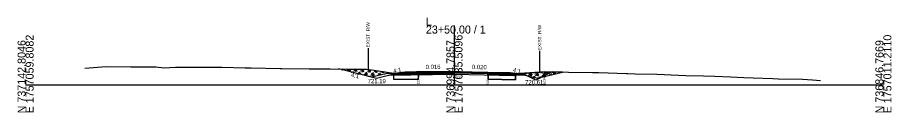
# Model space of a CAD drawing. Extents: x -26 to 4303, y -10 to 9577.
# Drawn here: x 997.2 to 1302.8, y 3490.3 to 3523.5 of the extents above; entities that cross this region are included whole.
import ezdxf

# ---------------------------------------------------------------- set-up
doc = ezdxf.new("R2010")
doc.units = 0
for name, color, linetype in [('Exist CMT Pavement', 7, 'Continuous'), ('Old_Level_10', 7, 'Continuous'), ('Old_Level_2', 7, 'Continuous'), ('Pattern 3', 7, 'Continuous'), ('Prop CMT Conc Surface', 7, 'Continuous'), ('Prop CMT Concrete Structures', 7, 'Continuous'), ('Prop CMT Concrete Wall', 7, 'Continuous'), ('Prop CMT Pvmt Course 1', 7, 'Continuous'), ('Prop CMT Pvmt Course 1 CG', 7, 'Continuous'), ('Prop CMT Pvmt Course 2', 7, 'Continuous'), ('Prop CMT Pvmt Course 2 Wedge', 7, 'Continuous'), ('Prop CMT Pvmt Course 3', 7, 'Continuous'), ('Prop CMT Pvmt Surface', 7, 'Continuous'), ('Prop CMT Pvmt Wedge Surface 1', 7, 'Continuous'), ('Prop CMT Shld Paved Course 1', 7, 'Continuous'), ('Prop CMT Shld Paved Course 2', 7, 'Continuous'), ('Prop CMT Shld Paved Course 3', 7, 'Continuous'), ('Prop CMT Slope Grass', 7, 'Continuous'), ('Prop CMT Subgrade Earthwork', 7, 'Continuous'), ('Prop Road Sect_ Recs - UC Shallow (Outline)', 7, 'Continuous'), ('Prop Shade Light', 7, 'Continuous'), ('Prop XS DDE Elevations', 7, 'Continuous'), ('Prop XS Ditch Standard Text', 7, 'Continuous'), ('Prop XS Earthwork Shape', 7, 'Continuous'), ('Prop XS Hydro Elevations', 7, 'Continuous'), ('Prop XS SE Text', 7, 'Continuous'), ('Prop XS Side Slope Text', 7, 'Continuous')]:
    doc.layers.add(name, color=color, linetype=linetype)

msp = doc.modelspace()

# ---------------------------------------------------------------- linework, layer by layer
at = {"layer": 'Exist CMT Pavement'}
for points in [[(1150, 3504.61), (1134.74, 3504.37)], [(1150, 3504.61), (1167.35, 3504.27)]]:
    msp.add_lwpolyline(points, dxfattribs=at)
at = {"layer": 'Old_Level_10'}
for p, q in [((1174.21, 3503.75), (1172.21, 3503.85)), ((1178.41, 3501.61), (1174.21, 3503.71)), ((1184.16, 3504.49), (1178.41, 3501.61))]:
    msp.add_line(p, q, dxfattribs=at)
at = {"layer": 'Old_Level_2'}
for p, q in [((1150, 3500), (1150, 3520.68)), ((1150, 3500), (1150, 3520.68)), ((1000, 3500), (1150, 3500)), ((1000, 3500), (1150, 3500)), ((1150, 3500), (1300, 3500)), ((1150, 3500), (1300, 3500))]:
    msp.add_line(p, q, dxfattribs=at)
at = {"layer": 'Pattern 3'}
for p, q in [((1110.45, 3505.26), (1111.3, 3505.49)), ((1110.6, 3505.5), (1110.97, 3505.13)), ((1110.8, 3505.49), (1110.72, 3505.19)), ((1112.51, 3505.06), (1113.72, 3505.38)), ((1112.87, 3505.47), (1113.55, 3504.78)), ((1113.18, 3505.46), (1112.95, 3504.63)), ((1113.91, 3504.43), (1113.95, 3504.38)), ((1114.51, 3504.59), (1114.42, 3504.27)), ((1114.86, 3504.94), (1116.07, 3505.27)), ((1114.93, 3504.14), (1114.95, 3504.15)), ((1115.12, 3505.46), (1115.91, 3504.66)), ((1115.56, 3505.45), (1115.31, 3504.5)), ((1116.26, 3504.31), (1116.93, 3503.64)), ((1116.37, 3503.78), (1117.31, 3504.03)), ((1116.87, 3504.47), (1116.66, 3503.71)), ((1117.22, 3504.82), (1118.43, 3505.15)), ((1117.38, 3505.43), (1118.27, 3504.54)), ((1117.95, 3505.44), (1117.66, 3504.38)), ((1118.46, 3503.59), (1119.67, 3503.91)), ((1118.62, 3504.19), (1119.5, 3503.31)), ((1119.22, 3504.35), (1118.9, 3503.15)), ((1119.58, 3504.71), (1120.78, 3505.03)), ((1119.74, 3505.31), (1120.62, 3504.43)), ((1120.3, 3505.3), (1120.02, 3504.26)), ((1120.46, 3503.11), (1120.37, 3502.78)), ((1120.81, 3503.47), (1122.02, 3503.79)), ((1120.98, 3504.07), (1121.86, 3503.19)), ((1121.58, 3504.23), (1121.26, 3503.03)), ((1121.93, 3504.59), (1123.1, 3504.9)), ((1122.26, 3505.03), (1122.98, 3504.31)), ((1122.6, 3504.98), (1122.38, 3504.15)), ((1123.17, 3503.35), (1124.38, 3503.67)), ((1123.33, 3503.95), (1123.93, 3503.35)), ((1123.94, 3504.12), (1123.72, 3503.3)), ((1124.29, 3504.47), (1124.87, 3504.62)), ((1124.89, 3504.62), (1124.73, 3504.03)), ((1124.91, 3504.62), (1125.34, 3504.19)), ((1125.69, 3503.84), (1125.72, 3503.8)), ((1126.29, 3504), (1126.26, 3503.86)), ((1127.18, 3504.27), (1127.09, 3503.91)), ((1127.55, 3504.21), (1127.69, 3504.07)), ((1128.65, 3503.88), (1128.65, 3503.87)), ((1129.48, 3503.92), (1129.47, 3503.87)), ((1130.03, 3503.97), (1130.05, 3503.95)), ((1131.93, 3504.15), (1131.86, 3503.87)), ((1132.07, 3504.16), (1132.36, 3503.87)), ((1133.72, 3504), (1134.92, 3504.32)), ((1134.12, 3504.35), (1134.6, 3503.88)), ((1134.38, 3504.38), (1134.24, 3503.88)), ((1136.09, 3503.88), (1137.28, 3504.2)), ((1136.23, 3504.48), (1136.83, 3503.88)), ((1136.83, 3504.6), (1136.63, 3503.88)), ((1162.38, 3504.15), (1162.28, 3503.77)), ((1162.69, 3504.13), (1162.89, 3503.93)), ((1163.84, 3503.74), (1163.82, 3503.64)), ((1164.73, 3503.99), (1164.64, 3503.65)), ((1165.09, 3503.96), (1165.24, 3503.81)), ((1166.2, 3503.62), (1166.19, 3503.59)), ((1167.07, 3503.82), (1167.01, 3503.57)), ((1167.5, 3503.79), (1167.6, 3503.69)), ((1169.42, 3503.65), (1169.38, 3503.53)), ((1169.85, 3503.68), (1169.95, 3503.58)), ((1171.27, 3503.74), (1171.49, 3503.8)), ((1171.85, 3503.82), (1171.76, 3503.48)), ((1171.94, 3503.83), (1172.3, 3503.47)), ((1173.62, 3503.62), (1174.83, 3503.94)), ((1174.03, 3503.98), (1174.67, 3503.34)), ((1174.28, 3504), (1174.13, 3503.43)), ((1175.62, 3503.15), (1175.61, 3503.1)), ((1175.98, 3503.5), (1177.19, 3503.82)), ((1176.14, 3504.1), (1177.02, 3503.22)), ((1176.72, 3504.17), (1176.42, 3503.06)), ((1177.55, 3504.24), (1177.54, 3504.18)), ((1178.33, 3503.38), (1179.54, 3503.71)), ((1178.5, 3503.99), (1179.38, 3503.1)), ((1179.1, 3504.15), (1178.78, 3502.94)), ((1179.99, 3504.41), (1179.9, 3504.06)), ((1180.29, 3504.43), (1180.5, 3504.22)), ((1180.69, 3503.26), (1181.9, 3503.59)), ((1180.85, 3503.87), (1181.74, 3502.98)), ((1181.46, 3504.03), (1181.13, 3502.82)), ((1181.81, 3504.38), (1182.31, 3504.52)), ((1182.41, 3504.52), (1182.25, 3503.94)), ((1182.44, 3504.52), (1182.86, 3504.1)), ((1183.21, 3503.75), (1183.57, 3503.39)), ((1183.81, 3503.91), (1183.68, 3503.42)), ((1184.17, 3504.26), (1184.95, 3504.47)), ((1184.78, 3504.48), (1184.61, 3503.82)), ((1184.72, 3504.48), (1185.21, 3503.98)), ((1186.52, 3504.15), (1187.58, 3504.43)), ((1186.99, 3504.44), (1187.15, 3504.29)), ((1187.16, 3504.44), (1187.12, 3504.28)), ((1119.86, 3502.95), (1119.92, 3502.89)), ((1120.85, 3502.66), (1120.9, 3502.67)), ((1177.38, 3502.87), (1177.66, 3502.58)), ((1177.98, 3503.03), (1177.85, 3502.54)), ((1178.05, 3502.49), (1178.42, 3502.59)), ((1179.73, 3502.75), (1179.99, 3502.5)), ((1180.34, 3502.91), (1180.24, 3502.56))]:
    msp.add_line(p, q, dxfattribs=at)
for points in [[(1121, 3502.62), (1109.45, 3505.51), (1113.28, 3505.46), (1119.26, 3505.44), (1121.87, 3505.09), (1125.66, 3504.5), (1129.45, 3503.92), (1133, 3504.25), (1136.84, 3504.6), (1137.45, 3504.64), (1137.45, 3503.89), (1129.62, 3503.87), (1128.62, 3503.87), (1125.95, 3503.86)], [(1179, 3502.25), (1187.72, 3504.43), (1181.59, 3504.53), (1178.1, 3504.28), (1172.9, 3503.9), (1169.41, 3503.65), (1166.49, 3503.86), (1163.07, 3504.1), (1161.77, 3504.19), (1161.77, 3503.68), (1171.39, 3503.49), (1174.28, 3503.43)]]:
    msp.add_lwpolyline(points, close=True, dxfattribs=at)
at = {"layer": 'Prop CMT Conc Surface'}
for points in [[(1137.37, 3504.16), (1134.74, 3504.12)], [(1134.74, 3504.12), (1134.74, 3503.91)], [(1134.74, 3503.91), (1137.37, 3503.96)], [(1137.37, 3503.96), (1137.37, 3504.16)], [(1161.69, 3503.92), (1161.69, 3504.13)], [(1161.69, 3504.13), (1167.35, 3504.02)], [(1167.35, 3503.81), (1161.69, 3503.92)], [(1167.35, 3504.02), (1167.35, 3503.81)]]:
    msp.add_lwpolyline(points, dxfattribs=at)
at = {"layer": 'Prop CMT Concrete Structures'}
for points in [[(1134.74, 3504.12), (1134.74, 3504.37)], [(1137.37, 3504.16), (1134.74, 3504.12)], [(1150, 3504.49), (1137.37, 3504.29)], [(1137.37, 3504.29), (1137.37, 3504.16)], [(1150, 3504.49), (1161.69, 3504.25)], [(1161.69, 3504.25), (1161.69, 3504.13)], [(1161.69, 3504.13), (1167.35, 3504.02)], [(1167.35, 3504.02), (1167.35, 3504.27)]]:
    msp.add_lwpolyline(points, dxfattribs=at)
at = {"layer": 'Prop CMT Pvmt Course 1'}
for points in [[(1137.37, 3503.96), (1134.74, 3503.91)], [(1134.74, 3503.91), (1134.74, 3503.58)], [(1134.74, 3503.58), (1137.37, 3503.62)], [(1137.37, 3503.96), (1150, 3504.16)], [(1137.37, 3503.62), (1137.37, 3503.96)], [(1161.69, 3503.92), (1150, 3504.16)], [(1161.69, 3503.92), (1167.35, 3503.81)], [(1161.69, 3503.59), (1161.69, 3503.92)], [(1167.35, 3503.47), (1161.69, 3503.59)], [(1167.35, 3503.81), (1167.35, 3503.47)]]:
    msp.add_lwpolyline(points, dxfattribs=at)
at = {"layer": 'Prop CMT Pvmt Course 2'}
for points in [[(1134.74, 3504.37), (1132.74, 3504.34), (1132.49, 3504.09)], [(1132.49, 3504.09), (1134.74, 3504.12)], [(1134.74, 3504.12), (1134.74, 3504.37)], [(1167.35, 3504.27), (1169.35, 3504.23), (1169.6, 3503.97)], [(1167.35, 3504.02), (1167.35, 3504.27)], [(1169.6, 3503.97), (1167.35, 3504.02)]]:
    msp.add_lwpolyline(points, dxfattribs=at)
at = {"layer": 'Prop CMT Pvmt Course 2 Wedge'}
for points in [[(1132.74, 3504.34), (1130.74, 3504.19), (1122.74, 3502.19), (1109.46, 3505.51)], [(1169.35, 3504.23), (1171.35, 3504.07), (1172.21, 3503.85)]]:
    msp.add_lwpolyline(points, dxfattribs=at)
at = {"layer": 'Prop CMT Pvmt Course 3'}
for points in [[(1134.74, 3504.12), (1132.49, 3504.09), (1132.28, 3503.87)], [(1132.28, 3503.87), (1134.74, 3503.91)], [(1134.74, 3503.91), (1134.74, 3504.12)], [(1167.35, 3504.02), (1169.6, 3503.97), (1169.82, 3503.76)], [(1167.35, 3503.81), (1167.35, 3504.02)], [(1169.82, 3503.76), (1167.35, 3503.81)]]:
    msp.add_lwpolyline(points, dxfattribs=at)
at = {"layer": 'Prop CMT Pvmt Surface'}
for points in [[(1134.74, 3504.12), (1134.74, 3504.37)], [(1150, 3504.36), (1134.74, 3504.12)], [(1150, 3504.36), (1167.35, 3504.02)], [(1167.35, 3504.02), (1167.35, 3504.27)]]:
    msp.add_lwpolyline(points, dxfattribs=at)
at = {"layer": 'Prop CMT Pvmt Wedge Surface 1'}
for p, q in [((1134.76, 3503.46), (1127.34, 3503.34)), ((1150, 3503.7), (1134.76, 3503.46)), ((1150, 3503.7), (1170.78, 3503.28)), ((1170.78, 3503.28), (1172.21, 3503.85))]:
    msp.add_line(p, q, dxfattribs=at)
at = {"layer": 'Prop CMT Shld Paved Course 1'}
for points in [[(1134.74, 3503.91), (1134.74, 3504.37)], [(1150, 3504.16), (1134.74, 3503.91)], [(1150, 3504.16), (1167.35, 3503.81)], [(1167.35, 3503.81), (1167.35, 3504.27)]]:
    msp.add_lwpolyline(points, dxfattribs=at)
at = {"layer": 'Prop CMT Shld Paved Course 2'}
for points in [[(1134.74, 3504.37), (1132.74, 3504.34)], [(1167.35, 3504.27), (1169.35, 3504.23)]]:
    msp.add_lwpolyline(points, dxfattribs=at)
at = {"layer": 'Prop CMT Shld Paved Course 3'}
for points in [[(1150, 3504.61), (1134.74, 3504.37)], [(1134.74, 3504.37), (1134.74, 3504.12)], [(1134.74, 3504.12), (1137.37, 3504.16)], [(1137.37, 3504.29), (1150, 3504.49)], [(1137.37, 3504.16), (1150, 3504.36)], [(1137.37, 3504.16), (1137.37, 3504.29)], [(1150, 3504.36), (1150, 3504.61)], [(1150, 3504.61), (1167.35, 3504.27)], [(1150, 3504.49), (1150, 3504.36), (1150, 3504.36)], [(1161.69, 3504.25), (1150, 3504.49)], [(1161.69, 3504.13), (1150, 3504.36)], [(1161.69, 3503.92), (1150, 3504.16)], [(1161.69, 3504.13), (1161.69, 3504.25)], [(1167.35, 3504.02), (1161.69, 3504.13)], [(1167.35, 3504.27), (1167.35, 3504.02)]]:
    msp.add_lwpolyline(points, dxfattribs=at)
at = {"layer": 'Prop CMT Slope Grass'}
msp.add_lwpolyline([(1020.7, 3505.76), (1028.18, 3506.41), (1036.85, 3506.31), (1038.32, 3506.28), (1045.56, 3506.25), (1048.45, 3505.94), (1052.48, 3506.11), (1058.59, 3506.17), (1064.61, 3506.18), (1068.72, 3506.16), (1076.73, 3505.91), (1078.86, 3505.88), (1088.99, 3505.64), (1089.66, 3505.64), (1099.13, 3505.59), (1106.5, 3505.55), (1112.37, 3505.47), (1119.18, 3505.44), (1121.82, 3505.09), (1129.37, 3503.92), (1136.75, 3504.6), (1137.55, 3504.66), (1138.19, 3504.63), (1140.04, 3504.61), (1140.92, 3504.6), (1143.06, 3504.59), (1143.45, 3504.59), (1145.43, 3504.57), (1146.09, 3504.56), (1148.52, 3504.54), (1149.12, 3504.53), (1150.03, 3504.53), (1150.4, 3504.52), (1151.05, 3504.52), (1152.15, 3504.48), (1153.58, 3504.44), (1155.18, 3504.4), (1156.12, 3504.39), (1158.22, 3504.29), (1158.82, 3504.27), (1159.57, 3504.26), (1160.57, 3504.24), (1161.21, 3504.21), (1161.9, 3504.18), (1163.19, 3504.09), (1169.32, 3503.65), (1172.8, 3503.89), (1181.51, 3504.53), (1198.22, 3504.25), (1200.48, 3504.26), (1210.11, 3503.89), (1210.61, 3503.87), (1213.14, 3503.83), (1220.75, 3503.7), (1228.38, 3503.31), (1230.88, 3503.23), (1237.08, 3503.1), (1241.02, 3502.96), (1246.49, 3502.75), (1251.15, 3502.53), (1254.5, 3502.41), (1261.29, 3502.18), (1263.2, 3502.11), (1271.65, 3501.89), (1275.23, 3501.71), (1278.03, 3501.46)], dxfattribs=at)
at = {"layer": 'Prop CMT Subgrade Earthwork'}
for points in [[(1134.74, 3503.91), (1132.28, 3503.87), (1131.78, 3503.87), (1131.44, 3503.53)], [(1131.44, 3503.53), (1134.74, 3503.58)], [(1134.74, 3503.58), (1134.74, 3503.91)], [(1167.35, 3503.81), (1169.82, 3503.76), (1170.32, 3503.75), (1170.66, 3503.41)], [(1167.35, 3503.47), (1167.35, 3503.81)], [(1170.66, 3503.41), (1167.35, 3503.47)]]:
    msp.add_lwpolyline(points, dxfattribs=at)
at = {"layer": 'Prop Road Sect_ Recs - UC Shallow (Outline)'}
for points in [[(1129.62, 3503.48), (1128.62, 3503.48), (1128.63, 3501.98), (1137.45, 3502), (1137.45, 3503.5)], [(1170.39, 3503.29), (1171.39, 3503.27), (1171.36, 3501.77), (1161.77, 3501.96), (1161.77, 3503.46)]]:
    msp.add_lwpolyline(points, close=True, dxfattribs=at)
at = {"layer": 'Prop Shade Light'}
for p, q in [((1129.62, 3503.48), (1128.62, 3503.48)), ((1128.62, 3503.48), (1128.63, 3501.98)), ((1137.45, 3502), (1137.45, 3503.5)), ((1161.77, 3503.46), (1161.77, 3501.96)), ((1171.39, 3503.27), (1170.73, 3503.28)), ((1171.36, 3501.77), (1171.39, 3503.27)), ((1128.63, 3501.98), (1137.45, 3502)), ((1161.77, 3501.96), (1171.36, 3501.77))]:
    msp.add_line(p, q, dxfattribs=at)
for points in [[(1137.45, 3503.5), (1133, 3503.49), (1129.62, 3503.48)], [(1170.73, 3503.28), (1167.43, 3503.35), (1161.77, 3503.46)]]:
    msp.add_lwpolyline(points, dxfattribs=at)
at = {"layer": 'Prop XS DDE Elevations'}
for points in [[(1121.82, 3505.09), (1129.37, 3503.92), (1129.83, 3503.96), (1127.34, 3503.34), (1122.74, 3502.19), (1109.46, 3505.51), (1112.37, 3505.47), (1119.18, 3505.44)], [(1134.74, 3504.37), (1134.21, 3504.36), (1129.83, 3503.96), (1127.34, 3503.34), (1134.76, 3503.46), (1150, 3503.7), (1170.78, 3503.28), (1172.21, 3503.85), (1169.32, 3503.65), (1163.19, 3504.09), (1161.9, 3504.18), (1161.21, 3504.21), (1160.57, 3504.24), (1159.57, 3504.26), (1158.82, 3504.27), (1158.22, 3504.29), (1156.12, 3504.39), (1155.18, 3504.4), (1153.58, 3504.44), (1152.15, 3504.48), (1151.05, 3504.52), (1150.4, 3504.52), (1150.03, 3504.53), (1149.12, 3504.53), (1148.52, 3504.54), (1146.44, 3504.56)], [(1134.74, 3504.37), (1134.21, 3504.36), (1136.75, 3504.6), (1137.55, 3504.66), (1138.19, 3504.63), (1140.04, 3504.61), (1140.92, 3504.6), (1143.06, 3504.59), (1143.45, 3504.59), (1145.43, 3504.57), (1146.09, 3504.56), (1146.44, 3504.56)]]:
    msp.add_lwpolyline(points, close=True, dxfattribs=at)
at = {"layer": 'Prop XS Ditch Standard Text'}
for p, q in [((1119.75, 3512.76), (1119.75, 3505.36)), ((1179.75, 3511.8), (1179.75, 3504.4)), ((1137.37, 3504.64), (1137.37, 3502.59)), ((1161.69, 3504.19), (1161.69, 3502.14)), ((1181.51, 3504.53), (1181.51, 3502.48))]:
    msp.add_line(p, q, dxfattribs=at)
at = {"layer": 'Prop XS Earthwork Shape'}
msp.add_lwpolyline([(1181.48, 3503.92), (1184.16, 3504.49), (1178.41, 3501.61), (1174.21, 3503.75), (1172.21, 3503.85), (1181.51, 3504.53), (1184.16, 3504.49)], close=True, dxfattribs=at)

# ---------------------------------------------------------------- texts
at = {"layer": 'Old_Level_2'}
for s, p in [('L', (1140, 3520.68)), ('L', (1140, 3520.68)), ('23+50.00 / 1', (1140, 3517.88)), ('23+50.00 / 1', (1140, 3517.88))]:
    msp.add_text(s, height=2.8, dxfattribs=at).set_placement(p)
for s, p in [('N 737142.8046', (1000, 3490)), ('N 737142.8046', (1000, 3490)), ('E 1757059.8082', (1002.8, 3490)), ('E 1757059.8082', (1002.8, 3490)), ('N 736994.7857', (1150, 3490)), ('N 736994.7857', (1150, 3490)), ('E 1757035.5096', (1152.8, 3490)), ('E 1757035.5096', (1152.8, 3490)), ('N 736846.7669', (1300, 3490)), ('N 736846.7669', (1300, 3490)), ('E 1757011.2110', (1302.8, 3490)), ('E 1757011.2110', (1302.8, 3490))]:
    msp.add_text(s, height=2.8, rotation=90, dxfattribs=at).set_placement(p)
at = {"layer": 'Prop CMT Concrete Wall'}
for rotation, p in [(334.1383, (1175.63, 3503.27)), (25.8617, (1179.06, 3502.19))]:
    msp.add_text('2:1', height=1.5, rotation=rotation, dxfattribs=at).set_placement(p)
msp.add_text('720.61', height=1.5, dxfattribs=at).set_placement((1174.72, 3500.14))
at = {"layer": 'Prop CMT Pvmt Course 1 CG'}
msp.add_text('723.53', height=1, dxfattribs=at).set_placement((1147.88, 3502.53))
at = {"layer": 'Prop XS Ditch Standard Text'}
for s, height, p in [('EXIST. R/W', 1.181, (1120.34, 3513.06)), ('EXIST. R/W', 1.181, (1180.35, 3512.11)), ('EOP', 0.787, (1137.76, 3500.2)), ('EOP', 0.787, (1162.08, 3499.74)), ('EOP', 0.787, (1181.9, 3500.08))]:
    msp.add_text(s, height=height, rotation=90, dxfattribs=at).set_placement(p)
at = {"layer": 'Prop XS Hydro Elevations'}
msp.add_text('721.19', height=1.5, dxfattribs=at).set_placement((1119.64, 3500.55))
at = {"layer": 'Prop XS SE Text'}
for s, rotation, p in [('0.016', 0.9071, (1139.92, 3505.45)), ('0.020', 358.8542, (1156.07, 3505.49))]:
    msp.add_text(s, height=1.5, rotation=rotation, dxfattribs=at).set_placement(p)
at = {"layer": 'Prop XS Side Slope Text'}
for rotation, p in [(345.9638, (1113.66, 3502.85)), (14.0362, (1128.78, 3503.96)), (345.9638, (1170.28, 3504.56))]:
    msp.add_text('4:1', height=1.5, rotation=rotation, dxfattribs=at).set_placement(p)

doc.saveas('drawing.dxf')
